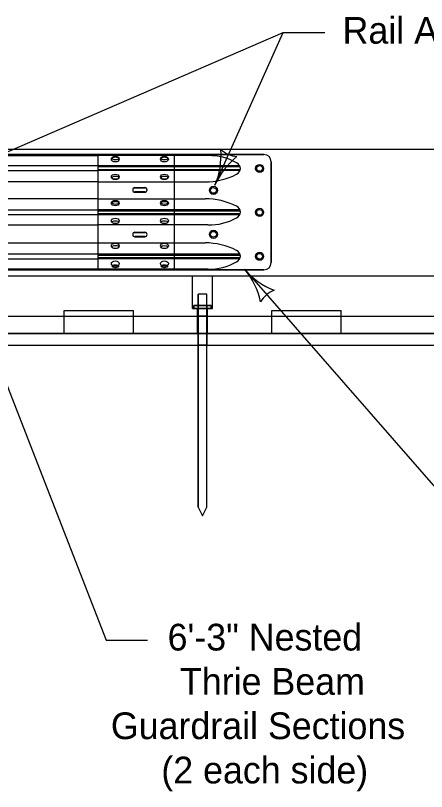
# Model space of a CAD drawing. Extents: x -2137026 to -2131464, y -2138478 to -2136524.
# Drawn here: x -2136540.6 to -2136307.1, y -2138375.3 to -2137934 of the extents above; entities that cross this region are included whole.
import ezdxf

# ---------------------------------------------------------------- set-up
doc = ezdxf.new("R2010")
doc.units = 0
for name, color, linetype in [('conPaving', 7, 'Continuous'), ('Level 2', 7, 'Continuous'), ('Level 3', 7, 'Continuous'), ('Level 41', 7, 'Continuous'), ('Level 9', 7, 'Continuous')]:
    doc.layers.add(name, color=color, linetype=linetype)

msp = doc.modelspace()

# ---------------------------------------------------------------- linework, layer by layer
at = {"layer": 'conPaving'}
for p, q in [((-2136493.65, -2138013.05), (-2136691.89, -2138013.05)), ((-2136399.44, -2138013.05), (-2136493.65, -2138013.05)), ((-2136395.34, -2138074.49), (-2136395.34, -2138017.14)), ((-2136472.76, -2138031.89), (-2136467.02, -2138031.89)), ((-2136467.02, -2138034.35), (-2136472.76, -2138034.35)), ((-2136472.76, -2138057.28), (-2136467.02, -2138057.28)), ((-2136467.02, -2138059.74), (-2136472.76, -2138059.74)), ((-2136691.89, -2138078.58), (-2136493.65, -2138078.58)), ((-2136493.65, -2138078.58), (-2136399.44, -2138078.58)), ((-2136436.72, -2138121.37), (-2136436.72, -2138114.82)), ((-2136431.43, -2138114.82), (-2136431.8, -2138114.82)), ((-2136431.8, -2138114.82), (-2136431.8, -2138121.37)), ((-2136269.98, -2138114.82), (-2136355.62, -2138114.82)), ((-2136554.36, -2138121.37), (-2136436.72, -2138121.37)), ((-2136431.8, -2138121.37), (-2136269.6, -2138121.37))]:
    msp.add_line(p, q, dxfattribs=at)
for points in [[(-2136436.72, -2138114.82), (-2136437.09, -2138114.82), (-2136473.58, -2138114.82), (-2136512.9, -2138114.82), (-2136556.91, -2138114.82)], [(-2136355.62, -2138114.82), (-2136394.94, -2138114.82), (-2136431.43, -2138114.82)]]:
    msp.add_lwpolyline(points, dxfattribs=at)
for centre, radius, start, end in [((-2136399.44, -2138017.14), 4.1, 0, 90), ((-2136472.76, -2138033.12), 1.23, 90, 270), ((-2136467.02, -2138033.12), 1.23, 270, 90), ((-2136472.76, -2138058.51), 1.23, 90, 270), ((-2136467.02, -2138058.51), 1.23, 270, 90), ((-2136399.44, -2138074.49), 4.1, 270, 0)]:
    msp.add_arc(centre, radius, start, end, dxfattribs=at)
at = {"layer": 'Level 2'}
for p, q in [((-2136589.27, -2138030.55), (-2136388.5, -2137943.65)), ((-2136427.28, -2138030.55), (-2136388.5, -2137943.65)), ((-2136388.5, -2137943.65), (-2136364.9, -2137943.65)), ((-2136680.02, -2138009.96), (-2136188.5, -2138009.96)), ((-2136410.46, -2138078.28), (-2136246.26, -2138266.62)), ((-2136680.02, -2138082.05), (-2136188.5, -2138082.05)), ((-2136569.88, -2138081.45), (-2136489.13, -2138289.19)), ((-2136680.02, -2138104.99), (-2136188.5, -2138104.99)), ((-2136512.9, -2138101.71), (-2136473.58, -2138101.71)), ((-2136512.9, -2138114.82), (-2136512.9, -2138104.99)), ((-2136473.58, -2138114.82), (-2136473.58, -2138104.99)), ((-2136394.94, -2138101.71), (-2136355.62, -2138101.71)), ((-2136394.94, -2138114.82), (-2136394.94, -2138104.99)), ((-2136355.62, -2138114.82), (-2136355.62, -2138104.99)), ((-2136679.78, -2138114.82), (-2136512.9, -2138114.82)), ((-2136473.58, -2138114.82), (-2136394.94, -2138114.82)), ((-2136355.62, -2138114.82), (-2136188.75, -2138114.82)), ((-2136489.13, -2138289.19), (-2136465.52, -2138289.19))]:
    msp.add_line(p, q, dxfattribs=at)
for centre, radius, start, end in [((-2136466.29, -2138013.67), 42.5, 336.6018, 4.6743), ((-2136413.13, -2137997.85), 16.42, 228.8685, 264.3352), ((-2136388.28, -2138047.43), 42.5, 128.5294, 156.6018), ((-2136442.81, -2138105.84), 42.5, 12.3611, 40.4336), ((-2136378.11, -2138050.71), 42.5, 220.4336, 248.5061), ((-2136387.35, -2138105.4), 16.42, 112.7003, 148.167)]:
    msp.add_arc(centre, radius, start, end, dxfattribs=at)
at = {"layer": 'Level 41'}
for p, q in [((-2136439.92, -2138100.62), (-2136439.92, -2138082.05)), ((-2136428.6, -2138100.62), (-2136428.6, -2138082.05)), ((-2136439.92, -2138100.62), (-2136428.6, -2138100.62)), ((-2136437.09, -2138114.82), (-2136437.09, -2138100.62)), ((-2136431.43, -2138114.82), (-2136431.43, -2138100.62))]:
    msp.add_line(p, q, dxfattribs=at)
at = {"layer": 'Level 9'}
for p, q in [((-2136493.65, -2138013.05), (-2136399.44, -2138013.05)), ((-2136493.65, -2138078.58), (-2136493.65, -2138013.05)), ((-2136450.23, -2138078.69), (-2136450.23, -2138013.16)), ((-2136395.34, -2138017.14), (-2136395.34, -2138074.49)), ((-2136395.34, -2138017.14), (-2136395.34, -2138074.49)), ((-2136413.18, -2138019.46), (-2136493.65, -2138019.46)), ((-2136412.96, -2138020.07), (-2136493.65, -2138020.07)), ((-2136493.65, -2138021.61), (-2136412.88, -2138021.61)), ((-2136413.05, -2138022.22), (-2136493.65, -2138022.22)), ((-2136413.05, -2138044.55), (-2136493.65, -2138044.55)), ((-2136493.65, -2138045.16), (-2136412.88, -2138045.16)), ((-2136412.96, -2138046.69), (-2136493.65, -2138046.69)), ((-2136413.18, -2138047.3), (-2136493.65, -2138047.3)), ((-2136413.05, -2138069.63), (-2136493.65, -2138069.63)), ((-2136493.65, -2138070.24), (-2136412.88, -2138070.24)), ((-2136412.96, -2138071.78), (-2136493.65, -2138071.78)), ((-2136413.18, -2138072.39), (-2136493.65, -2138072.39)), ((-2136691.89, -2138078.58), (-2136493.65, -2138078.58)), ((-2136691.89, -2138078.58), (-2136493.65, -2138078.58)), ((-2136399.44, -2138078.58), (-2136493.65, -2138078.58)), ((-2136431.8, -2138092.42), (-2136436.72, -2138092.42)), ((-2136436.72, -2138092.42), (-2136436.72, -2138098.98)), ((-2136431.8, -2138092.42), (-2136436.72, -2138092.42)), ((-2136436.72, -2138213.67), (-2136436.72, -2138092.42)), ((-2136431.8, -2138098.98), (-2136431.8, -2138092.42)), ((-2136431.8, -2138213.67), (-2136431.8, -2138092.42)), ((-2136439.18, -2138098.98), (-2136439.18, -2138100.62)), ((-2136436.72, -2138098.98), (-2136439.18, -2138098.98)), ((-2136439.18, -2138100.62), (-2136439.18, -2138098.98)), ((-2136439.18, -2138100.62), (-2136437.09, -2138100.62)), ((-2136437.09, -2138100.62), (-2136436.72, -2138100.62)), ((-2136431.8, -2138098.98), (-2136436.72, -2138098.98)), ((-2136436.72, -2138098.98), (-2136436.72, -2138100.62)), ((-2136436.72, -2138100.62), (-2136436.72, -2138098.98)), ((-2136436.72, -2138098.98), (-2136431.8, -2138098.98)), ((-2136431.8, -2138100.62), (-2136436.72, -2138100.62)), ((-2136436.72, -2138100.62), (-2136436.72, -2138104.99)), ((-2136436.72, -2138100.62), (-2136431.8, -2138100.62)), ((-2136431.8, -2138100.62), (-2136431.8, -2138098.98)), ((-2136431.8, -2138098.98), (-2136431.8, -2138100.62)), ((-2136431.8, -2138104.99), (-2136431.8, -2138100.62)), ((-2136512.9, -2138104.99), (-2136512.9, -2138101.71)), ((-2136512.9, -2138104.99), (-2136473.58, -2138104.99)), ((-2136473.58, -2138104.99), (-2136473.58, -2138101.71)), ((-2136431.8, -2138104.99), (-2136436.72, -2138104.99)), ((-2136436.72, -2138104.99), (-2136436.72, -2138114.82)), ((-2136436.72, -2138104.99), (-2136431.8, -2138104.99)), ((-2136431.8, -2138114.82), (-2136431.8, -2138104.99)), ((-2136394.94, -2138104.99), (-2136394.94, -2138101.71)), ((-2136394.94, -2138104.99), (-2136355.62, -2138104.99)), ((-2136355.62, -2138104.99), (-2136355.62, -2138101.71)), ((-2136987.54, -2138114.82), (-2134196.38, -2138114.82)), ((-2136431.8, -2138114.82), (-2136436.72, -2138114.82)), ((-2136436.72, -2138114.82), (-2136436.72, -2138121.37)), ((-2136436.72, -2138114.82), (-2136431.8, -2138114.82)), ((-2136431.8, -2138121.37), (-2136431.8, -2138114.82)), ((-2136691.9, -2138121.37), (-2134672.37, -2138121.37)), ((-2136431.8, -2138121.37), (-2136436.72, -2138121.37)), ((-2136436.72, -2138121.37), (-2136436.72, -2138213.67)), ((-2136436.72, -2138121.37), (-2136431.8, -2138121.37)), ((-2136431.8, -2138213.67), (-2136431.8, -2138121.37)), ((-2136436.72, -2138213.67), (-2136434.26, -2138218.58)), ((-2136436.72, -2138213.67), (-2136434.26, -2138218.58)), ((-2136434.26, -2138218.58), (-2136431.8, -2138213.67)), ((-2136434.26, -2138218.58), (-2136431.8, -2138213.67))]:
    msp.add_line(p, q, dxfattribs=at)
for points in [[(-2136691.89, -2138013.05), (-2136493.65, -2138013.05)], [(-2136691.89, -2138013.54), (-2136493.65, -2138013.54)], [(-2136431.24, -2138013.65), (-2136493.65, -2138013.65)], [(-2136691.89, -2138019.35), (-2136493.65, -2138019.35)], [(-2136691.89, -2138022.11), (-2136493.65, -2138022.11)], [(-2136691.89, -2138028.46), (-2136493.65, -2138028.46)], [(-2136493.65, -2138028.57), (-2136432.87, -2138028.57)], [(-2136472.76, -2138032), (-2136467.02, -2138032)], [(-2136467.02, -2138032), (-2136472.76, -2138032)], [(-2136472.76, -2138032), (-2136467.02, -2138032)], [(-2136467.02, -2138032), (-2136472.76, -2138032)], [(-2136467.02, -2138034.46), (-2136472.76, -2138034.46)], [(-2136472.76, -2138034.46), (-2136467.02, -2138034.46)], [(-2136467.02, -2138034.46), (-2136472.76, -2138034.46)], [(-2136472.76, -2138034.46), (-2136467.02, -2138034.46)], [(-2136691.89, -2138038.08), (-2136493.65, -2138038.08)], [(-2136493.65, -2138038.2), (-2136432.87, -2138038.2)], [(-2136691.89, -2138044.43), (-2136493.65, -2138044.43)], [(-2136691.89, -2138047.19), (-2136493.65, -2138047.19)], [(-2136691.89, -2138053), (-2136493.65, -2138053)], [(-2136431.24, -2138053.11), (-2136493.65, -2138053.11)], [(-2136472.76, -2138057.39), (-2136467.02, -2138057.39)], [(-2136467.02, -2138057.39), (-2136472.76, -2138057.39)], [(-2136472.76, -2138057.39), (-2136467.02, -2138057.39)], [(-2136467.02, -2138057.39), (-2136472.76, -2138057.39)], [(-2136467.02, -2138059.85), (-2136472.76, -2138059.85)], [(-2136472.76, -2138059.85), (-2136467.02, -2138059.85)], [(-2136467.02, -2138059.85), (-2136472.76, -2138059.85)], [(-2136472.76, -2138059.85), (-2136467.02, -2138059.85)], [(-2136691.89, -2138063.17), (-2136493.65, -2138063.17)], [(-2136493.65, -2138063.28), (-2136432.87, -2138063.28)], [(-2136691.89, -2138069.52), (-2136493.65, -2138069.52)], [(-2136691.89, -2138072.28), (-2136493.65, -2138072.28)], [(-2136691.89, -2138078.09), (-2136493.65, -2138078.09)], [(-2136431.24, -2138078.2), (-2136493.65, -2138078.2)], [(-2136439.18, -2138098.98), (-2136429.35, -2138098.98), (-2136429.35, -2138100.62), (-2136439.18, -2138100.62)], [(-2136429.35, -2138100.62), (-2136429.35, -2138098.98), (-2136431.8, -2138098.98)], [(-2136431.8, -2138100.62), (-2136431.43, -2138100.62), (-2136429.35, -2138100.62)]]:
    msp.add_lwpolyline(points, dxfattribs=at)
for centre, radius in [((-2136401.9, -2138020.96), 2.3), ((-2136401.9, -2138020.96), 1.64), ((-2136401.9, -2138020.96), 1.64), ((-2136428.11, -2138033.43), 2.3), ((-2136428.11, -2138033.43), 1.64), ((-2136428.11, -2138033.43), 1.64), ((-2136401.9, -2138045.94), 2.3), ((-2136401.9, -2138045.94), 1.64), ((-2136401.9, -2138045.94), 1.64), ((-2136428.11, -2138058.42), 2.3), ((-2136428.11, -2138058.42), 1.64), ((-2136428.11, -2138058.42), 1.64), ((-2136401.9, -2138070.91), 2.3), ((-2136401.9, -2138070.91), 1.64), ((-2136401.9, -2138070.91), 1.64)]:
    msp.add_circle(centre, radius, dxfattribs=at)
for centre, radius, start, end in [((-2136399.44, -2138017.14), 4.1, 0, 90), ((-2136399.44, -2138017.14), 4.1, 0, 90), ((-2136430.77, -2138046.36), 32.71, 61.1095, 90.8177), ((-2136416.42, -2138021), 3.59, 293.8801, 66.1199), ((-2136432.83, -2137989.2), 39.37, 269.944, 296.985), ((-2136472.76, -2138033.23), 1.23, 90, 270), ((-2136472.76, -2138033.23), 1.23, 90, 270), ((-2136472.76, -2138033.23), 1.23, 90, 270), ((-2136472.76, -2138033.23), 1.23, 90, 270), ((-2136467.02, -2138033.23), 1.23, 270, 90), ((-2136467.02, -2138033.23), 1.23, 270, 90), ((-2136467.02, -2138033.23), 1.23, 270, 90), ((-2136467.02, -2138033.23), 1.23, 270, 90), ((-2136432.83, -2138077.57), 39.37, 63.015, 90.056), ((-2136416.42, -2138045.76), 3.59, 293.8801, 66.1199), ((-2136430.77, -2138020.41), 32.71, 269.1823, 298.8905), ((-2136472.76, -2138058.62), 1.23, 90, 270), ((-2136472.76, -2138058.62), 1.23, 90, 270), ((-2136472.76, -2138058.62), 1.23, 90, 270), ((-2136472.76, -2138058.62), 1.23, 90, 270), ((-2136467.02, -2138058.62), 1.23, 270, 90), ((-2136467.02, -2138058.62), 1.23, 270, 90), ((-2136467.02, -2138058.62), 1.23, 270, 90), ((-2136467.02, -2138058.62), 1.23, 270, 90), ((-2136432.83, -2138102.65), 39.37, 63.015, 90.056), ((-2136416.42, -2138070.85), 3.59, 293.8801, 66.1199), ((-2136430.77, -2138045.49), 32.71, 269.1823, 298.8905), ((-2136399.44, -2138074.49), 4.1, 270, 0), ((-2136399.44, -2138074.49), 4.1, 270, 0)]:
    msp.add_arc(centre, radius, start, end, dxfattribs=at)
for centre, major_axis, ratio in [((-2136483.86, -2138015.68), (2.26, 0), 0.685714), ((-2136483.82, -2138015.26), (1.84, 0), 0.456281), ((-2136455.99, -2138015.68), (2.26, 0), 0.685714), ((-2136455.98, -2138015.25), (1.84, 0), 0.456281), ((-2136483.86, -2138025.78), (2.26, 0), 0.685714), ((-2136483.8, -2138026.21), (1.84, 0), 0.456281), ((-2136455.99, -2138025.78), (2.26, 0), 0.685714), ((-2136455.96, -2138026.2), (1.84, 0), 0.456281), ((-2136483.86, -2138040.68), (2.26, 0), 0.685714), ((-2136483.8, -2138040.56), (1.84, 0), 0.456281), ((-2136455.99, -2138040.68), (2.26, 0), 0.685714), ((-2136455.96, -2138040.56), (1.84, 0), 0.456281), ((-2136483.86, -2138050.77), (2.26, 0), 0.685714), ((-2136483.82, -2138051.51), (1.84, 0), 0.456281), ((-2136455.99, -2138050.77), (2.26, 0), 0.685714), ((-2136455.98, -2138051.52), (1.84, 0), 0.456281), ((-2136483.86, -2138065.02), (2.26, 0), 0.685714), ((-2136483.8, -2138065.64), (1.84, 0), 0.456281), ((-2136455.99, -2138065.02), (2.26, 0), 0.685714), ((-2136455.96, -2138065.65), (1.84, 0), 0.456281), ((-2136483.86, -2138075.11), (2.26, 0), 0.685714), ((-2136455.99, -2138075.11), (2.26, 0), 0.685714), ((-2136483.82, -2138076.59), (1.84, 0), 0.456281), ((-2136455.98, -2138076.6), (1.84, 0), 0.456281)]:
    msp.add_ellipse(centre, major_axis=major_axis, ratio=ratio, dxfattribs=at)

# ---------------------------------------------------------------- texts
at = {"layer": 'Level 3'}
for s, p in [('Rail Anchor Bolt', (-2136354.76, -2137950)), ('6\'-3" Nested', (-2136454.17, -2138295.12)), ('Thrie Beam', (-2136447.13, -2138320.32)), ('Guardrail Sections', (-2136486.39, -2138345.52)), ('(2 each side)', (-2136457.72, -2138370.72))]:
    msp.add_text(s, height=15.2, dxfattribs=at).set_placement(p)

doc.saveas('drawing.dxf')
